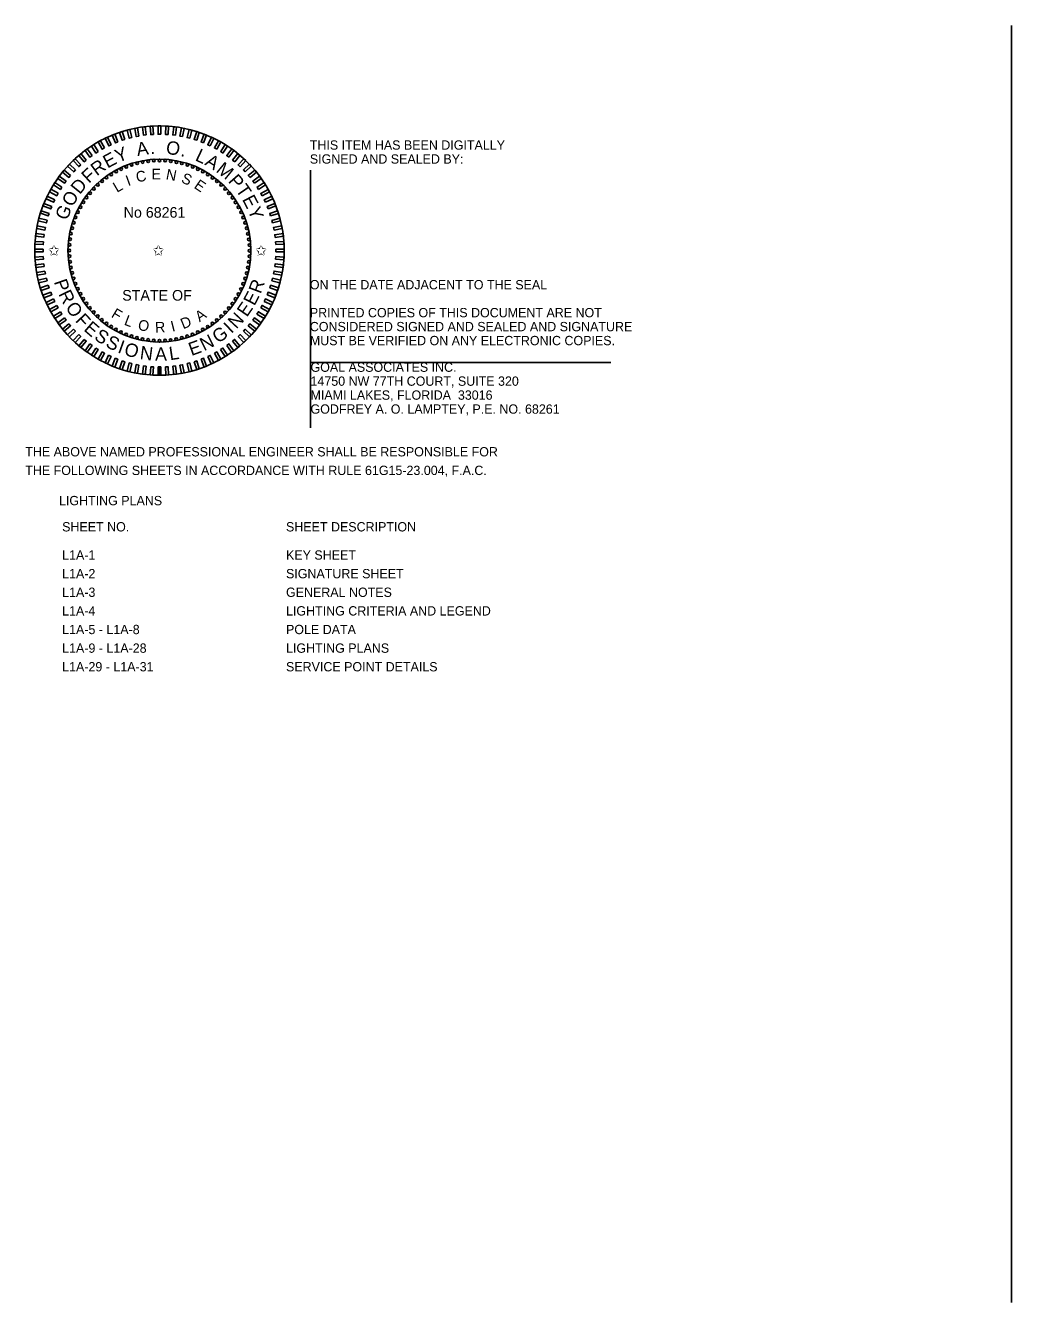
# Model space of a CAD drawing. Extents: x -811.2 to -795.1, y -2238.2 to -2204.
# Drawn here: x -810.5 to -803.09, y -2213.6 to -2204 of the extents above; entities that cross this region are included whole.
import ezdxf

# ---------------------------------------------------------------- set-up
doc = ezdxf.new("R2010")
doc.units = 0
for name, color, linetype in [('AdhocPoint_dp', 7, 'Continuous'), ('PlotBorder_dp', 7, 'Continuous'), ('TextMinor', 7, 'Continuous'), ('TextMisc', 7, 'Continuous'), ('TextNotes', 7, 'Continuous'), ('TextShtNo', 7, 'Continuous')]:
    doc.layers.add(name, color=color, linetype=linetype)

msp = doc.modelspace()

# ---------------------------------------------------------------- linework, layer by layer
at = {"layer": 'AdhocPoint_dp'}
for p, q in [((-808.3546, -2205.0892), (-808.3546, -2207.0239)), ((-808.3546, -2206.5339), (-806.0979, -2206.5339))]:
    msp.add_line(p, q, dxfattribs=at)
at = {"layer": 'TextMinor'}
for radius in [0.9375, 0.6875]:
    msp.add_circle((-809.4901, -2205.6926), radius, dxfattribs=at)
at = {"layer": 'TextNotes'}
msp.add_line((-803.0858, -2213.6006), (-803.0858, -2204.0006), dxfattribs=at)
at = {"layer": 'TextShtNo'}
for p, q in [((-809.5001, -2206.6301), (-809.5003, -2206.5676)), ((-809.4901, -2206.6301), (-809.4903, -2206.5676)), ((-809.4801, -2206.6301), (-809.4803, -2206.5676))]:
    msp.add_line(p, q, dxfattribs=at)
for points in [[(-809.8028, -2204.8753), (-809.8215, -2204.8827), (-809.8445, -2204.8246), (-809.8258, -2204.8172)], [(-809.7508, -2204.8572), (-809.77, -2204.8635), (-809.7893, -2204.8041), (-809.7701, -2204.7979)], [(-809.6979, -2204.8425), (-809.7174, -2204.8475), (-809.7329, -2204.7871), (-809.7134, -2204.782)], [(-809.6441, -2204.8312), (-809.6639, -2204.8349), (-809.6756, -2204.7736), (-809.6558, -2204.7698)], [(-809.5897, -2204.8232), (-809.6097, -2204.8257), (-809.6175, -2204.7638), (-809.5975, -2204.7612)], [(-809.5349, -2204.8187), (-809.555, -2204.8199), (-809.559, -2204.7576), (-809.5388, -2204.7563)], [(-809.4799, -2204.8176), (-809.5001, -2204.8176), (-809.5001, -2204.7551), (-809.4799, -2204.7551)], [(-809.425, -2204.8199), (-809.4452, -2204.8187), (-809.4412, -2204.7563), (-809.4211, -2204.7576)], [(-809.3703, -2204.8257), (-809.3904, -2204.8232), (-809.3825, -2204.7613), (-809.3625, -2204.7638)], [(-809.3162, -2204.835), (-809.336, -2204.8312), (-809.3243, -2204.7699), (-809.3045, -2204.7736)], [(-809.2626, -2204.8476), (-809.2822, -2204.8426), (-809.2667, -2204.7821), (-809.2471, -2204.7871)], [(-809.21, -2204.8635), (-809.2292, -2204.8573), (-809.2099, -2204.7979), (-809.1907, -2204.8042)], [(-809.1585, -2204.8828), (-809.1773, -2204.8753), (-809.1543, -2204.8173), (-809.1355, -2204.8247)], [(-809.9504, -2204.9483), (-809.9674, -2204.9591), (-810.0009, -2204.9064), (-809.9838, -2204.8956)], [(-809.9027, -2204.9209), (-809.9204, -2204.9306), (-809.9505, -2204.8759), (-809.9328, -2204.8662)], [(-809.8535, -2204.8965), (-809.8717, -2204.9051), (-809.8983, -2204.8486), (-809.8801, -2204.84)], [(-809.1083, -2204.9052), (-809.1266, -2204.8966), (-809.1, -2204.8401), (-809.0817, -2204.8487)], [(-809.0596, -2204.9307), (-809.0773, -2204.921), (-809.0473, -2204.8663), (-809.0296, -2204.876)], [(-809.0127, -2204.9592), (-809.0297, -2204.9484), (-808.9962, -2204.8957), (-808.9792, -2204.9065)], [(-810.0817, -2205.0478), (-810.0964, -2205.0616), (-810.1392, -2205.0161), (-810.1244, -2205.0022)], [(-810.04, -2205.0119), (-810.0556, -2205.0247), (-810.0954, -2204.9766), (-810.0798, -2204.9638)], [(-809.9962, -2204.9787), (-810.0125, -2204.9906), (-810.0492, -2204.94), (-810.0329, -2204.9282)], [(-808.9676, -2204.9907), (-808.9839, -2204.9788), (-808.9472, -2204.9283), (-808.9308, -2204.9402)], [(-808.9245, -2205.0249), (-808.9401, -2205.012), (-808.9003, -2204.9639), (-808.8847, -2204.9768)], [(-808.8837, -2205.0617), (-808.8984, -2205.0479), (-808.8557, -2205.0024), (-808.841, -2205.0162)], [(-810.1579, -2205.127), (-810.1707, -2205.1425), (-810.2188, -2205.1027), (-810.206, -2205.0872)], [(-810.121, -2205.0862), (-810.1348, -2205.1009), (-810.1804, -2205.0581), (-810.1665, -2205.0434)], [(-808.8453, -2205.101), (-808.8591, -2205.0863), (-808.8136, -2205.0436), (-808.7998, -2205.0583)], [(-808.8094, -2205.1427), (-808.8223, -2205.1271), (-808.7742, -2205.0873), (-808.7613, -2205.1029)], [(-810.2235, -2205.2151), (-810.2343, -2205.2322), (-810.287, -2205.1987), (-810.2762, -2205.1817)], [(-810.192, -2205.17), (-810.2039, -2205.1864), (-810.2544, -2205.1497), (-810.2426, -2205.1333)], [(-808.7762, -2205.1865), (-808.7881, -2205.1702), (-808.7376, -2205.1335), (-808.7257, -2205.1498)], [(-808.7459, -2205.2323), (-808.7567, -2205.2153), (-808.7039, -2205.1818), (-808.6931, -2205.1989)], [(-810.2775, -2205.3108), (-810.2861, -2205.3291), (-810.3426, -2205.3025), (-810.334, -2205.2842)], [(-810.252, -2205.2621), (-810.2617, -2205.2798), (-810.3164, -2205.2497), (-810.3067, -2205.232)], [(-808.7184, -2205.28), (-808.7281, -2205.2623), (-808.6734, -2205.2322), (-808.6637, -2205.2499)], [(-808.694, -2205.3292), (-808.7026, -2205.311), (-808.6461, -2205.2844), (-808.6375, -2205.3027)], [(-810.3192, -2205.4125), (-810.3254, -2205.4317), (-810.3848, -2205.4124), (-810.3786, -2205.3932)], [(-810.3, -2205.361), (-810.3074, -2205.3798), (-810.3654, -2205.3568), (-810.358, -2205.338)], [(-808.6728, -2205.3799), (-808.6802, -2205.3612), (-808.6222, -2205.3382), (-808.6147, -2205.357)], [(-808.6548, -2205.4319), (-808.661, -2205.4127), (-808.6016, -2205.3934), (-808.5954, -2205.4126)], [(-810.3351, -2205.4651), (-810.3401, -2205.4847), (-810.4006, -2205.4691), (-810.3956, -2205.4496)], [(-808.64, -2205.4849), (-808.6451, -2205.4653), (-808.5846, -2205.4498), (-808.5796, -2205.4693)], [(-810.357, -2205.5728), (-810.3595, -2205.5928), (-810.4215, -2205.585), (-810.4189, -2205.565)], [(-810.3477, -2205.5186), (-810.3515, -2205.5385), (-810.4129, -2205.5268), (-810.4091, -2205.5069)], [(-808.6287, -2205.5386), (-808.6325, -2205.5188), (-808.5711, -2205.5071), (-808.5673, -2205.5269)], [(-808.6207, -2205.593), (-808.6232, -2205.573), (-808.5613, -2205.5652), (-808.5588, -2205.5852)], [(-810.3652, -2205.6824), (-810.3652, -2205.7026), (-810.4276, -2205.7026), (-810.4276, -2205.6824)], [(-810.3628, -2205.6275), (-810.3641, -2205.6476), (-810.4264, -2205.6437), (-810.4251, -2205.6236)], [(-808.6162, -2205.6478), (-808.6174, -2205.6277), (-808.5551, -2205.6238), (-808.5539, -2205.6439)], [(-808.6151, -2205.7028), (-808.6151, -2205.6826), (-808.5527, -2205.6826), (-808.5527, -2205.7028)], [(-810.3641, -2205.7374), (-810.3628, -2205.7575), (-810.4251, -2205.7614), (-810.4264, -2205.7413)], [(-808.6175, -2205.7577), (-808.6162, -2205.7376), (-808.5539, -2205.7415), (-808.5551, -2205.7616)], [(-810.3595, -2205.7922), (-810.357, -2205.8122), (-810.4189, -2205.82), (-810.4215, -2205.8)], [(-810.3516, -2205.8466), (-810.3478, -2205.8664), (-810.4091, -2205.8781), (-810.4129, -2205.8583)], [(-808.6325, -2205.8666), (-808.6287, -2205.8467), (-808.5674, -2205.8584), (-808.5712, -2205.8783)], [(-808.6233, -2205.8124), (-808.6207, -2205.7923), (-808.5588, -2205.8002), (-808.5613, -2205.8202)], [(-810.3402, -2205.9003), (-810.3352, -2205.9199), (-810.3957, -2205.9354), (-810.4007, -2205.9159)], [(-810.3255, -2205.9533), (-810.3192, -2205.9725), (-810.3786, -2205.9918), (-810.3849, -2205.9726)], [(-808.6611, -2205.9727), (-808.6548, -2205.9535), (-808.5954, -2205.9728), (-808.6017, -2205.992)], [(-808.6451, -2205.9201), (-808.6401, -2205.9005), (-808.5796, -2205.916), (-808.5846, -2205.9356)], [(-810.3075, -2206.0052), (-810.3, -2206.024), (-810.3581, -2206.047), (-810.3655, -2206.0282)], [(-810.2862, -2206.0559), (-810.2776, -2206.0742), (-810.3341, -2206.1008), (-810.3427, -2206.0825)], [(-808.7027, -2206.0744), (-808.6941, -2206.0561), (-808.6376, -2206.0827), (-808.6462, -2206.101)], [(-808.6803, -2206.0242), (-808.6729, -2206.0054), (-808.6148, -2206.0284), (-808.6222, -2206.0472)], [(-810.2618, -2206.1052), (-810.2521, -2206.1229), (-810.3068, -2206.153), (-810.3165, -2206.1353)], [(-810.2344, -2206.1529), (-810.2236, -2206.1699), (-810.2763, -2206.2034), (-810.2871, -2206.1863)], [(-808.7568, -2206.1701), (-808.746, -2206.153), (-808.6932, -2206.1865), (-808.704, -2206.2035)], [(-808.7282, -2206.1231), (-808.7185, -2206.1054), (-808.6638, -2206.1355), (-808.6735, -2206.1532)], [(-810.204, -2206.1987), (-810.1922, -2206.215), (-810.2427, -2206.2517), (-810.2545, -2206.2354)], [(-810.1708, -2206.2425), (-810.158, -2206.2581), (-810.2061, -2206.2979), (-810.2189, -2206.2823)], [(-808.8224, -2206.2582), (-808.8095, -2206.2427), (-808.7614, -2206.2825), (-808.7743, -2206.298)], [(-808.7882, -2206.2152), (-808.7763, -2206.1988), (-808.7258, -2206.2355), (-808.7377, -2206.2519)], [(-810.135, -2206.2842), (-810.1211, -2206.2989), (-810.1667, -2206.3416), (-810.1805, -2206.3269)], [(-810.0965, -2206.3235), (-810.0818, -2206.3373), (-810.1246, -2206.3828), (-810.1393, -2206.369)], [(-810.0557, -2206.3603), (-810.0402, -2206.3732), (-810.08, -2206.4213), (-810.0955, -2206.4084)], [(-808.9402, -2206.3733), (-808.9247, -2206.3604), (-808.8848, -2206.4086), (-808.9004, -2206.4214)], [(-808.8985, -2206.3374), (-808.8838, -2206.3236), (-808.8411, -2206.3691), (-808.8558, -2206.383)], [(-808.8592, -2206.299), (-808.8454, -2206.2843), (-808.7999, -2206.327), (-808.8137, -2206.3418)], [(-810.0127, -2206.3945), (-809.9964, -2206.4064), (-810.0331, -2206.4569), (-810.0494, -2206.445)], [(-809.9676, -2206.426), (-809.9505, -2206.4368), (-809.984, -2206.4895), (-810.001, -2206.4787)], [(-809.9206, -2206.4545), (-809.9029, -2206.4642), (-809.933, -2206.5189), (-809.9507, -2206.5092)], [(-809.0775, -2206.4643), (-809.0598, -2206.4546), (-809.0297, -2206.5093), (-809.0474, -2206.519)], [(-809.0299, -2206.4369), (-809.0128, -2206.4261), (-808.9794, -2206.4788), (-808.9964, -2206.4896)], [(-808.984, -2206.4065), (-808.9677, -2206.3946), (-808.931, -2206.4451), (-808.9473, -2206.457)], [(-809.8719, -2206.48), (-809.8536, -2206.4886), (-809.8802, -2206.5451), (-809.8985, -2206.5365)], [(-809.8217, -2206.5024), (-809.8029, -2206.5099), (-809.8259, -2206.5679), (-809.8447, -2206.5605)], [(-809.7702, -2206.5217), (-809.751, -2206.5279), (-809.7703, -2206.5873), (-809.7895, -2206.581)], [(-809.7176, -2206.5376), (-809.698, -2206.5426), (-809.7136, -2206.6031), (-809.7331, -2206.5981)], [(-809.6641, -2206.5502), (-809.6443, -2206.554), (-809.656, -2206.6153), (-809.6758, -2206.6116)], [(-809.6099, -2206.5594), (-809.5899, -2206.562), (-809.5977, -2206.6239), (-809.6177, -2206.6214)], [(-809.3906, -2206.562), (-809.3705, -2206.5595), (-809.3627, -2206.6214), (-809.3827, -2206.624)], [(-809.3362, -2206.554), (-809.3163, -2206.5503), (-809.3046, -2206.6116), (-809.3245, -2206.6154)], [(-809.2824, -2206.5427), (-809.2628, -2206.5376), (-809.2473, -2206.5981), (-809.2668, -2206.6031)], [(-809.2294, -2206.5279), (-809.2102, -2206.5217), (-809.1909, -2206.5811), (-809.2101, -2206.5873)], [(-809.1775, -2206.5099), (-809.1587, -2206.5025), (-809.1357, -2206.5606), (-809.1545, -2206.568)], [(-809.1268, -2206.4887), (-809.1085, -2206.4801), (-809.0819, -2206.5366), (-809.1002, -2206.5452)], [(-809.5552, -2206.5653), (-809.5351, -2206.5665), (-809.539, -2206.6288), (-809.5592, -2206.6276)], [(-809.5003, -2206.5676), (-809.4801, -2206.5676), (-809.4801, -2206.6301), (-809.5003, -2206.6301)], [(-809.4453, -2206.5665), (-809.4252, -2206.5653), (-809.4213, -2206.6276), (-809.4414, -2206.6289)]]:
    msp.add_lwpolyline(points, close=True, dxfattribs=at)
for centre in [(-809.6165, -2205.027), (-809.5745, -2205.0204), (-809.5321, -2205.0164), (-809.4896, -2205.0151), (-809.447, -2205.0165), (-809.4047, -2205.0205), (-809.3626, -2205.0272), (-809.8527, -2205.1203), (-809.816, -2205.0987), (-809.7781, -2205.0794), (-809.739, -2205.0625), (-809.6989, -2205.0481), (-809.6581, -2205.0363), (-809.3211, -2205.0366), (-809.2802, -2205.0485), (-809.2402, -2205.0629), (-809.2012, -2205.0798), (-809.1633, -2205.0992), (-809.1266, -2205.1209), (-809.9535, -2205.1984), (-809.9215, -2205.1702), (-809.8879, -2205.1442), (-809.0915, -2205.1448), (-809.0579, -2205.171), (-809.026, -2205.1991), (-810.0379, -2205.2939), (-810.0118, -2205.2603), (-809.9836, -2205.2284), (-808.9959, -2205.2292), (-808.9678, -2205.2612), (-808.9417, -2205.2948), (-810.1029, -2205.4036), (-810.0835, -2205.3657), (-810.0618, -2205.3291), (-808.9178, -2205.3301), (-808.8962, -2205.3667), (-808.8769, -2205.4047), (-810.1343, -2205.4827), (-810.1198, -2205.4427), (-808.86, -2205.4437), (-808.8456, -2205.4838), (-810.1622, -2205.6071), (-810.1555, -2205.5651), (-810.1462, -2205.5236), (-808.8338, -2205.5247), (-808.8245, -2205.5662), (-808.8179, -2205.6082), (-810.1676, -2205.692), (-810.1662, -2205.6495), (-808.814, -2205.6506), (-808.8127, -2205.6932), (-810.1663, -2205.7346), (-810.1623, -2205.7769), (-808.8181, -2205.7781), (-808.814, -2205.7357), (-810.1557, -2205.819), (-810.1464, -2205.8605), (-808.8341, -2205.8616), (-808.8248, -2205.8201), (-810.1346, -2205.9014), (-810.1202, -2205.9415), (-810.1034, -2205.9805), (-808.8774, -2205.9816), (-808.8604, -2205.9425), (-808.846, -2205.9025), (-810.0841, -2206.0185), (-810.0624, -2206.0551), (-808.9184, -2206.0561), (-808.8967, -2206.0195), (-810.0385, -2206.0903), (-810.0125, -2206.124), (-809.9844, -2206.1559), (-808.9967, -2206.1568), (-808.9685, -2206.1249), (-808.9424, -2206.0913), (-809.9543, -2206.1861), (-809.9224, -2206.2142), (-809.8888, -2206.2403), (-809.8536, -2206.2643), (-809.1276, -2206.2649), (-809.0924, -2206.241), (-809.0587, -2206.215), (-809.0268, -2206.1868), (-809.817, -2206.286), (-809.7791, -2206.3053), (-809.74, -2206.3223), (-809.7, -2206.3367), (-809.6591, -2206.3486), (-809.6176, -2206.358), (-809.5756, -2206.3647), (-809.5332, -2206.3687), (-809.4901, -2206.3701), (-809.4481, -2206.3688), (-809.4058, -2206.3648), (-809.3637, -2206.3582), (-809.3222, -2206.3489), (-809.2813, -2206.3371), (-809.2413, -2206.3227), (-809.2022, -2206.3058), (-809.1642, -2206.2865)]:
    msp.add_circle(centre, 0.01, dxfattribs=at)

# ---------------------------------------------------------------- texts
at = {"layer": 'PlotBorder_dp'}
for s, p in [('THIS ITEM HAS BEEN DIGITALLY', (-808.3596, -2204.934)), ('SIGNED AND SEALED BY:', (-808.3596, -2205.039)), ('ON THE DATE ADJACENT TO THE SEAL', (-808.3596, -2205.984)), ('PRINTED COPIES OF THIS DOCUMENT ARE NOT ', (-808.3596, -2206.194)), ('CONSIDERED SIGNED AND SEALED AND SIGNATURE ', (-808.3596, -2206.299)), ('MUST BE VERIFIED ON ANY ELECTRONIC COPIES.', (-808.3596, -2206.404)), ('GOAL ASSOCIATES INC.', (-808.3546, -2206.6039)), ('14750 NW 77TH COURT, SUITE 320', (-808.3546, -2206.7089)), ('MIAMI LAKES, FLORIDA  33016', (-808.3546, -2206.8139)), ('GODFREY A. O. LAMPTEY, P.E. NO. 68261', (-808.3546, -2206.9189)), ('THE ABOVE NAMED PROFESSIONAL ENGINEER SHALL BE RESPONSIBLE FOR ', (-810.4987, -2207.24)), ('THE FOLLOWING SHEETS IN ACCORDANCE WITH RULE 61G15-23.004, F.A.C.', (-810.4987, -2207.38)), ('LIGHTING PLANS', (-810.245, -2207.6071))]:
    msp.add_text(s, height=0.07, dxfattribs=at).set_placement(p)
at = {"layer": 'TextMisc'}
for s, p in [('SHEET NO.', (-810.2215, -2207.8041)), ('SHEET DESCRIPTION', (-808.5387, -2207.8041)), ('L1A-1', (-810.2215, -2208.0162)), ('KEY SHEET', (-808.5387, -2208.0162)), ('L1A-2', (-810.2215, -2208.1562)), ('SIGNATURE SHEET', (-808.5387, -2208.1562)), ('L1A-3', (-810.2215, -2208.2962)), ('GENERAL NOTES', (-808.5387, -2208.2962)), ('L1A-4', (-810.2215, -2208.4362)), ('LIGHTING CRITERIA AND LEGEND', (-808.5387, -2208.4362)), ('L1A-5 - L1A-8', (-810.2215, -2208.5762)), ('POLE DATA', (-808.5387, -2208.5762)), ('L1A-9 - L1A-28', (-810.2215, -2208.7162)), ('LIGHTING PLANS', (-808.5387, -2208.7162)), ('L1A-29 - L1A-31', (-810.2215, -2208.8562)), ('SERVICE POINT DETAILS', (-808.5387, -2208.8562))]:
    msp.add_text(s, height=0.07, dxfattribs=at).set_placement(p)
at = {"layer": 'TextShtNo'}
for s, height, rotation, p in [('Y', 0.1, 21.06329, (-809.8021, -2205.0332)), ('A', 0.1, 8.80884, (-809.6551, -2204.982)), ('O', 0.1, 352.18771, (-809.4449, -2204.9645)), ('L', 0.1, 334.67271, (-809.2279, -2205.0118)), ('R', 0.1, 35.92688, (-809.9609, -2205.1353)), ('E', 0.1, 28.10553, (-809.8806, -2205.0764)), ('.', 0.1, 1.04184, (-809.5575, -2204.9662)), ('.', 0.1, 343.52684, (-809.3358, -2204.9796)), ('A', 0.1, 328.40959, (-809.1552, -2205.0445)), ('F', 0.1, 42.37723, (-810.0205, -2205.1917)), ('C', 0.08, 12.20255, (-809.6579, -2205.181)), ('E', 0.08, 0.41861, (-809.5498, -2205.1575)), ('N', 0.08, 349.29143, (-809.4455, -2205.1561)), ('S', 0.08, 337.02207, (-809.3325, -2205.1778)), ('M', 0.1, 320.6426, (-809.0707, -2205.0957)), ('P', 0.1, 311.19658, (-808.9784, -2205.1727)), ('D', 0.1, 50.8569, (-810.0886, -2205.2754)), ('L', 0.08, 30.40215, (-809.8093, -2205.259)), ('I', 0.08, 20.01168, (-809.7258, -2205.2085)), ('E', 0.08, 325.86633, (-809.2358, -2205.218)), ('T', 0.1, 304.45632, (-808.9209, -2205.2363)), ('O', 0.1, 59.51777, (-810.1446, -2205.3702)), ('E', 0.1, 297.63152, (-808.8707, -2205.3072)), ('G', 0.1, 68.0518, (-810.1851, -2205.4709)), ('Y', 0.1, 290.58928, (-808.8281, -2205.386)), ('P', 0.1, 289.40551, (-810.2848, -2205.9272)), ('R', 0.1, 69.5134, (-808.7299, -2206.0223)), ('R', 0.1, 296.14576, (-810.2518, -2206.0188)), ('E', 0.1, 55.42892, (-808.833, -2206.1974)), ('E', 0.1, 62.47116, (-808.7761, -2206.113)), ('O', 0.1, 303.96711, (-810.2003, -2206.1194)), ('F', 0.1, 312.62798, (-810.1279, -2206.2215)), ('F', 0.08, 328.72408, (-809.8582, -2206.1892)), ('A', 0.08, 34.49917, (-809.1883, -2206.232)), ('N', 0.1, 47.17876, (-808.9123, -2206.2864)), ('E', 0.1, 319.07833, (-810.0645, -2206.2898)), ('L', 0.08, 339.29159, (-809.7609, -2206.2483)), ('O', 0.08, 349.68206, (-809.6562, -2206.288)), ('R', 0.08, 2.33977, (-809.5217, -2206.3099)), ('I', 0.08, 14.20366, (-809.3941, -2206.3032)), ('D', 0.08, 22.01279, (-809.312, -2206.2845)), ('G', 0.1, 35.11153, (-809.0492, -2206.3941)), ('I', 0.1, 43.64556, (-808.9499, -2206.3209)), ('S', 0.1, 326.12056, (-809.9869, -2206.3557)), ('S', 0.1, 333.193, (-809.9015, -2206.4119)), ('I', 0.1, 340.26543, (-809.8098, -2206.457)), ('E', 0.1, 19.81912, (-809.2498, -2206.4856)), ('N', 0.1, 26.86136, (-809.1544, -2206.4501)), ('O', 0.1, 343.79863, (-809.7621, -2206.4753)), ('N', 0.1, 352.45949, (-809.6411, -2206.5073)), ('A', 0.1, 0.70966, (-809.5227, -2206.5206)), ('L', 0.1, 8.47665, (-809.4105, -2206.5174))]:
    msp.add_text(s, height=height, rotation=rotation, dxfattribs=at).set_placement(p)
for s, p in [('No 68261', (-809.7591, -2205.4454)), ('✩', (-810.3251, -2205.7305)), ('✩', (-809.5404, -2205.7305)), ('✩', (-808.7685, -2205.7305)), ('STATE OF', (-809.7698, -2206.0688))]:
    msp.add_text(s, height=0.08, dxfattribs=at).set_placement(p)

doc.saveas('drawing.dxf')
